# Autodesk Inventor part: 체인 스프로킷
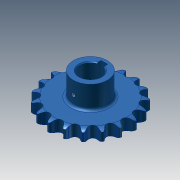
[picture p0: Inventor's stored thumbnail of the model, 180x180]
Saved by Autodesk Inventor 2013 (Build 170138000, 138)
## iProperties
Created: 2014-07
Part Number: 체인 스프로킷
Material: 강
Document SubType Name: Modeling
Designer: KYOUNG IL JANG
Density: 7.85 g/cm^3
Mass: 738.6 g
Surface Area: 236.854 cm^2
Volume: 94.0892 cm^3
Company: 한국ATC센터
Author: KYOUNG IL JANG
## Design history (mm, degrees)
sketch "이론적 톱니 프로파일"
  geometry: L1 (0, 0)-(0, 45.567); L2 (0, 0)-(14.795, 43.098); L3 (0, 45.567)-(14.795, 43.098); L4 (0, 45.567)-(5.661, 50.015); L5 (5.661, 50.015)-(-5.141, 45.406); L6 (-12.428, 43.493)-(-5.573, 46.417); L7 (-5.141, 45.406)-(-5.573, 46.417); L8 (5.573, 46.417)-(5.141, 45.406); L9 (0, 0)-(8.138, 48.771); A1 r 45.567 centre (0, 0) between (0, 45.567) and (14.795, 43.098); A2 r 49.445 centre (0, 0) between (7.302, 48.903) and (-7.302, 48.903); A3 r 4.545 centre (0, 45.567) between (-3.574, 42.758) and (3.574, 42.758); A4 r 7.453 centre (12.428, 43.493) between (7.302, 48.903) and (5.573, 46.417); A5 r 7.453 centre (-12.428, 43.493) between (-5.573, 46.417) and (-7.302, 48.903); A6 r 11.745 centre (5.661, 50.015) between (-5.141, 45.406) and (-3.574, 42.758); A7 r 11.745 centre (-5.661, 50.015) between (3.574, 42.758) and (5.141, 45.406); 2 further points
  constraints: 18 end point, 15 point on circle, 7 centre point, 3 coincident, 3 point on line, 3 symmetric about line, 3 tangent, 1 equal radius, 1 midpoint, 1 parallel, 1 vertical, 1 other
  dimensions: "d0" = 91.13301 diameter of A1 (computed from da_p, da_z); "d2" = 18.9474 deg angle of L2 L1 (computed from da_z); "d3" = 4.545 radius of A3 (= 0.5 x da_Dr + da_SC); "d10" = 128.158 deg angle of L4 L1 (computed from da_z); "d11" = 15.0526 deg angle of L5 L4 (computed from da_z); "d12" = 7.2 distance of L3.start L4.end (= 0.8 x da_Dr); "d13" = 11.745 distance of L4.end L5.end (= 1.3 x da_Dr + da_SC); "d14" = 12.6 distance of A4.centre L1.end (= 1.4 x da_Dr); "d23" = 4.5 distance from line of L9.end L3 (= da_Ha)
sketch "톱니 프로파일"
  geometry: L1 (0, 0)-(0, 45.567); L2 (0, 45.567)-(4.203, 43.837); L3 (0, 45.567)-(-4.203, 43.837); A1 r 4.545 centre (0, 45.567) between (-4.203, 43.837) and (4.203, 43.837); A2 r 22.68 centre (25.176, 35.206) between (7.12, 48.93) and (4.203, 43.837); A3 r 22.68 centre (-25.176, 35.206) between (-4.203, 43.837) and (-7.12, 48.93); A4 r 49.445 centre (0, 0) between (-7.12, 48.93) and (7.12, 48.93) reference; 1 further point
  constraints: 9 point on circle, 6 end point, 3 centre point, 2 tangent, 1 coincident, 1 equal radius, 1 vertical, 1 other
  dimensions: "d44" = 135.263 deg angle of L3 L2 (= da_Alfa); "d45" = 22.68 radius of A2 (= da_Re); "d46" = 4.545 radius of A1 (= da_Ri)
sketch "단면 프로파일"
  geometry: L1 (49.445, 0)-(-49.445, 0) reference; L2 (33.265, 6.65)-(-33.265, 6.65); L3 (-33.265, 6.65)-(-33.265, -6.65); L4 (-33.265, -6.65)-(33.265, -6.65); L5 (33.265, -6.65)-(33.265, 6.65); L6 (33.265, 6.65)-(49.445, 6.65); L7 (49.445, 6.65)-(49.445, -6.65); L8 (49.445, -6.65)-(33.265, -6.65); L9 (33.265, -6.65)-(33.265, 6.65); L10 (42.183, 6.65)-(0, 6.65); L11 (0, 6.65)-(0, -6.65); L12 (0, -6.65)-(42.183, -6.65); L13 (0, 6.65)-(0, -6.65); L14 (49.445, 4.775)-(49.445, -4.775); A1 r 15 centre (42.183, -8.35) between (49.445, 4.775) and (42.183, 6.65); A2 r 15 centre (42.183, 8.35) between (42.183, -6.65) and (49.445, -4.775); 2 further points
  constraints: 26 end point, 7 midpoint, 5 perpendicular, 4 parallel, 4 point on circle, 3 point on line, 3 symmetric about line, 2 centre point, 2 horizontal, 2 tangent, 1 collinear, 1 other
  dimensions: "d30" = 13.3 distance between parallel lines of L8 L6 (= da_Bf); "d31" = 66.53007 distance between parallel lines of L3 L5 (= da_Ds); "d32" = 13.3 distance between parallel lines of L4 L2 (= da_Bs); "d33" = 1.875 distance from line of L14.start L6 (= da_Ba); "d34" = 15 radius of A1 (= da_Rx); "d43" = 6.65 distance between parallel lines of L4 L1 (computed from da_k, da_pt, da_Bs)
revolve "슈라우드" stored, may be unused: angle "d36" = 90 deg
revolve "스트랜드" stored, may be unused: angle "d37" = 90 deg
extrude "이론적 톱니" cut sketch "이론적 톱니 프로파일" stored distance "d18" = 10; taper "d19" = 0 deg; dims "d49" = 0, "form_type" = 0 [user parameter]
extrude "톱니" cut sketch "톱니 프로파일" stored distance "d47" = 10; taper "d48" = 0 deg; dims "d50" = 10, "form_type" = 0 [user parameter]
node "타이밍 평면"
node "작업 평면3"
sketch "스케치5"
  geometry: C1 r 20 at (0, -45.567); 1 further point
  constraints: 1 centre point, 1 coincident
  dimensions: "d52" = 40 diameter of C1
extrude "돌출4" join sketch "스케치5" stored distance "d53" = 10; taper "d54" = 0 deg
sketch "스케치6"
  geometry: L1 (4, 11.843)-(4, 16.5); L2 (4, 16.5)-(-4, 16.5); L3 (-4, 16.5)-(-4, 11.843); A1 r 12.5 centre (0, 0) between (4, 11.843) and (-4, 11.843); 1 further point
  constraints: 6 end point, 2 parallel, 2 point on circle, 1 centre point, 1 coincident, 1 perpendicular, 1 vertical
  dimensions: "d55" = 25 diameter of A1; "d56" = 29 dimension on A1 L2 (computed from d55); "d57" = 8 distance of L1.end L2.end
extrude "돌출5" cut sketch "스케치6" stored distance "d58" = 10; taper "d59" = 0 deg
fillet "모깎기2" dims "d60" = 3
chamfer "모따기1" distance "d61" = 1; stored, may be unused: second distance "d62" = 2, angle "d63" = 45 deg
node "작업 평면4"
sketch "스케치7"
  geometry: L1 (-13.5, -13.3)-(13.5, -13.3) reference; 4 further points
  constraints: 1 vertical alignment
  dimensions: "d65" = 25 distance from line of point (0, 11.7) L1
hole "구멍1" sketch "스케치7" at (0, 11.7) diameter "d66" = 4.134; stored, may be unused: countersink angle "d70" = 90 deg, drill point angle "d72" = 118 deg; dims "d67" = 6, "d68" = 4, "d69" = 2, "d71" = 8
body "Solid1"
pattern_linear "스트랜드 패턴" dims "d40" = 24 (= da_pt)
pattern_circular "톱니 패턴" dims angle "d21" = 360 deg
other parameters: "da_p" = 15 [user parameter; used in 1 equation term], "da_Dr" = 9 [user parameter; used in 4 equation terms], "da_SC" = 0.045 [user parameter; used in 2 equation terms], "da_Ha" = 4.5 [user parameter; used in 1 equation term], "da_pt" = 24 [user parameter; used in 2 equation terms], "da_Bf" = 13.3 [user parameter; used in 1 equation term], "d28" = 0, "d29" = 0, "da_Ba" = 1.875 [user parameter; used in 1 equation term], "da_Rx" = 15 [user parameter; used in 1 equation term], "da_Ra" = 0.6 [user parameter], "da_Bs" = 13.3 [user parameter; used in 2 equation terms], "da_Ds" = 66.53007 [user parameter; used in 1 equation term], "d42" = 0, "da_Re" = 22.68 [user parameter; used in 1 equation term], "da_Ri" = 4.545 [user parameter; used in 1 equation term], "da_Alfa" = 135.263 deg [user parameter; used in 1 equation term]
